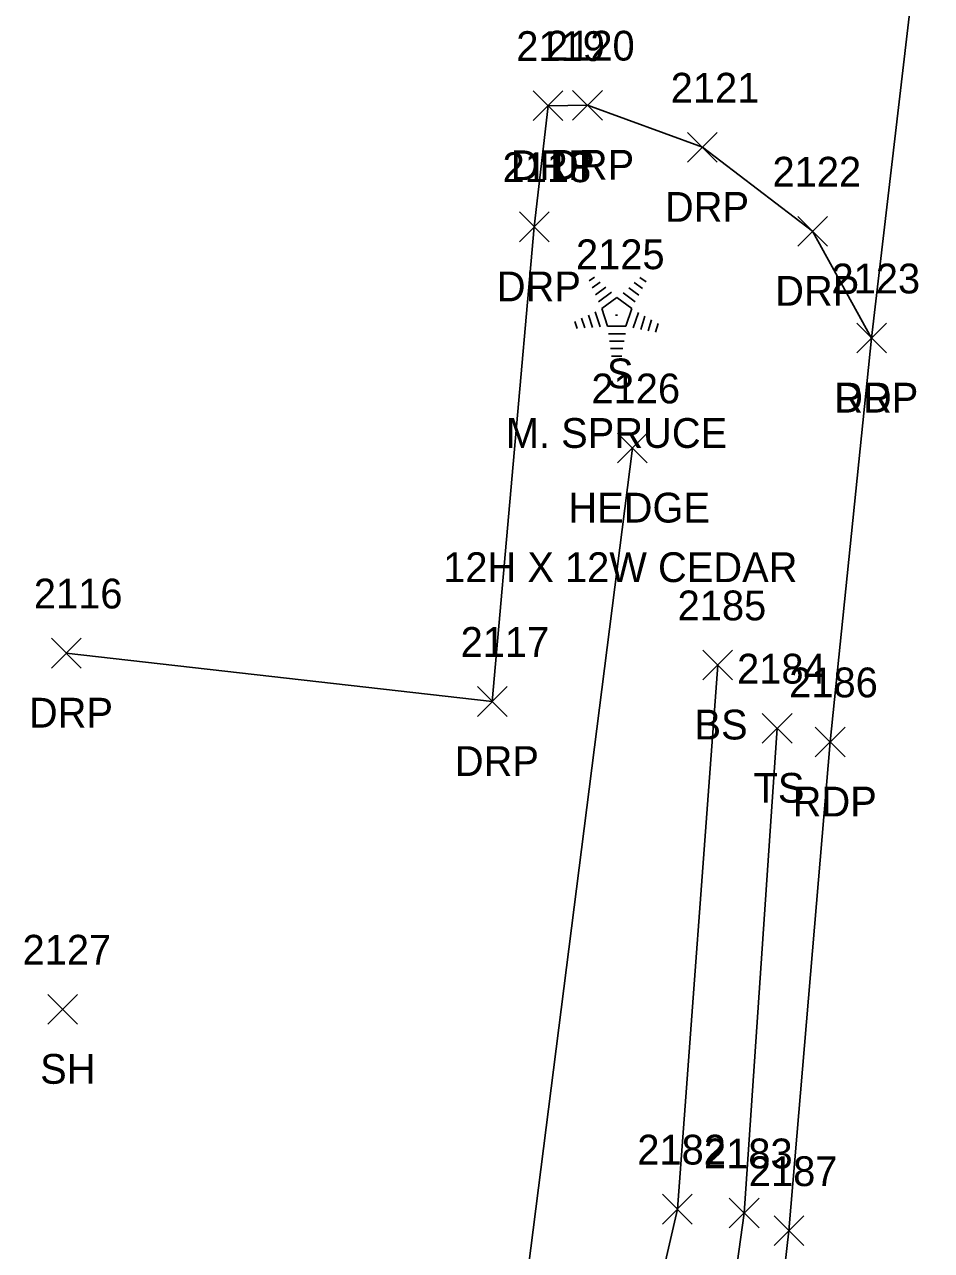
# Model space of a CAD drawing. Extents: x 1651305 to 1654558, y 539481 to 548441.
# Drawn here: x 1654302.3 to 1654363.2, y 544215.2 to 544297.6 of the extents above; entities that cross this region are included whole.
import ezdxf

# ---------------------------------------------------------------- set-up
doc = ezdxf.new("R2010")
doc.units = 0
for name, color, linetype in [('L_A', 7, 'Continuous'), ('L_C', 7, 'Continuous'), ('L_I', 7, 'Continuous'), ('L_TIC', 7, 'Continuous'), ('LAHR', 7, 'Continuous'), ('LELB', 7, 'Continuous'), ('LTC', 7, 'Continuous'), ('P_A', 7, 'Continuous'), ('P_I', 7, 'Continuous'), ('P_TIC', 7, 'Continuous'), ('PET', 7, 'Continuous'), ('R_A', 7, 'Continuous'), ('R_I', 7, 'Continuous'), ('R_TIC', 7, 'Continuous'), ('RDP', 7, 'Continuous')]:
    doc.layers.add(name, color=color, linetype=linetype)

msp = doc.modelspace()

# ---------------------------------------------------------------- linework, layer by layer
at = {"layer": 'L_TIC'}
for points in [[(1654342.12, 544268.118), (1654344.12, 544270.118)], [(1654344.12, 544268.118), (1654342.12, 544270.118)], [(1654347.847, 544253.55), (1654349.847, 544255.55)], [(1654349.847, 544253.55), (1654347.847, 544255.55)], [(1654351.841, 544249.303), (1654353.841, 544251.303)], [(1654353.841, 544249.303), (1654351.841, 544251.303)], [(1654303.88, 544230.43), (1654305.88, 544232.43)], [(1654305.88, 544230.43), (1654303.88, 544232.43)], [(1654345.141, 544217.007), (1654347.141, 544219.007)], [(1654347.141, 544217.007), (1654345.141, 544219.007)], [(1654349.618, 544216.751), (1654351.618, 544218.751)], [(1654351.618, 544216.751), (1654349.618, 544218.751)]]:
    msp.add_lwpolyline(points, dxfattribs=at)
at = {"layer": 'LAHR'}
msp.add_lwpolyline([(1654343.12, 544269.118), (1654333.903, 544196.537)], dxfattribs=at)
at = {"layer": 'LELB'}
for points in [[(1654340.212, 544192.32), (1654346.141, 544218.007), (1654348.847, 544254.55)], [(1654335.349, 544184.471), (1654346.097, 544185.222), (1654350.618, 544217.751), (1654352.841, 544250.303)]]:
    msp.add_lwpolyline(points, dxfattribs=at)
at = {"layer": 'LTC'}
for p, q in [((1654340.22, 544280.338), (1654340.575, 544280.596)), ((1654343.618, 544280.579), (1654344.038, 544280.274)), ((1654340.43, 544279.873), (1654340.959, 544280.257)), ((1654340.639, 544279.407), (1654341.343, 544279.918)), ((1654342.876, 544279.882), (1654343.555, 544279.388)), ((1654343.247, 544280.23), (1654343.797, 544279.831)), ((1654340.849, 544278.941), (1654341.727, 544279.579)), ((1654341.073, 544278.486), (1654342.085, 544279.221)), ((1654342.085, 544279.221), (1654343.082, 544278.496)), ((1654342.505, 544279.534), (1654343.315, 544278.945)), ((1654340.163, 544278.051), (1654340.435, 544277.216)), ((1654340.619, 544278.267), (1654340.95, 544277.248)), ((1654341.073, 544278.486), (1654341.46, 544277.293)), ((1654343.082, 544278.496), (1654342.691, 544277.293)), ((1654343.52, 544278.225), (1654343.182, 544277.186)), ((1654343.964, 544277.975), (1654343.677, 544277.09)), ((1654339.253, 544277.618), (1654339.405, 544277.15)), ((1654339.708, 544277.834), (1654339.92, 544277.183)), ((1654342.691, 544277.293), (1654341.46, 544277.293)), ((1654344.409, 544277.725), (1654344.172, 544276.995)), ((1654344.853, 544277.474), (1654344.666, 544276.9)), ((1654342.653, 544276.793), (1654341.508, 544276.793)), ((1654342.569, 544276.293), (1654341.58, 544276.293)), ((1654342.485, 544275.793), (1654341.653, 544275.793)), ((1654342.401, 544275.293), (1654341.726, 544275.293))]:
    msp.add_line(p, q, dxfattribs=at)
at = {"layer": 'P_TIC'}
for points in [[(1654358.176, 544275.501), (1654360.176, 544277.501)], [(1654360.176, 544275.501), (1654358.176, 544277.501)], [(1654355.39, 544248.38), (1654357.39, 544250.38)], [(1654357.39, 544248.38), (1654355.39, 544250.38)], [(1654352.626, 544215.56), (1654354.626, 544217.56)], [(1654354.626, 544215.56), (1654352.626, 544217.56)]]:
    msp.add_lwpolyline(points, dxfattribs=at)
at = {"layer": 'PET'}
msp.add_lwpolyline([(1654345.042, 544588.36), (1654352.836, 544566.031), (1654357.709, 544551.643), (1654360.669, 544540.213), (1654367.97, 544503.911), (1654371.191, 544473.217), (1654373.313, 544432.687), (1654372.374, 544396.626), (1654369.948, 544367.404), (1654366.855, 544341.544), (1654364.487, 544322.02), (1654359.176, 544276.501), (1654356.39, 544249.38), (1654353.626, 544216.56), (1654349.272, 544178.191), (1654347.294, 544164.707), (1654345.692, 544149.484), (1654340.924, 544117.477), (1654336.045, 544077.134)], dxfattribs=at)
at = {"layer": 'R_TIC'}
for points in [[(1654336.457, 544291.109), (1654338.457, 544293.109)], [(1654338.457, 544291.109), (1654336.457, 544293.109)], [(1654339.103, 544291.136), (1654341.103, 544293.136)], [(1654341.103, 544291.136), (1654339.103, 544293.136)], [(1654346.817, 544288.313), (1654348.817, 544290.313)], [(1654348.817, 544288.313), (1654346.817, 544290.313)], [(1654335.532, 544282.973), (1654337.532, 544284.973)], [(1654337.532, 544282.973), (1654335.532, 544284.973)], [(1654354.217, 544282.673), (1654356.217, 544284.673)], [(1654356.217, 544282.673), (1654354.217, 544284.673)], [(1654358.176, 544275.501), (1654360.176, 544277.501)], [(1654360.176, 544275.501), (1654358.176, 544277.501)], [(1654304.127, 544254.348), (1654306.127, 544256.348)], [(1654306.127, 544254.348), (1654304.127, 544256.348)], [(1654332.714, 544251.098), (1654334.714, 544253.098)], [(1654334.714, 544251.098), (1654332.714, 544253.098)]]:
    msp.add_lwpolyline(points, dxfattribs=at)
at = {"layer": 'RDP'}
msp.add_lwpolyline([(1654305.127, 544255.348), (1654333.714, 544252.098), (1654336.532, 544283.973), (1654337.457, 544292.109), (1654340.103, 544292.136), (1654347.817, 544289.313), (1654355.217, 544283.673), (1654359.176, 544276.501)], dxfattribs=at)

# ---------------------------------------------------------------- texts
at = {"layer": 'L_A'}
for s, p in [('S', (1654341.411, 544273.13)), ('HEDGE', (1654338.821, 544264.118)), ('BS', (1654347.288, 544249.55)), ('TS', (1654351.251, 544245.303)), ('SH', (1654303.368, 544226.43))]:
    msp.add_text(s, height=2, dxfattribs=at).set_placement(p)
at = {"layer": 'L_C'}
for s, p in [('M. SPRUCE', (1654334.623, 544269.13)), ('12H X 12W CEDAR', (1654330.42, 544260.118))]:
    msp.add_text(s, height=2, dxfattribs=at).set_placement(p)
at = {"layer": 'L_I'}
for s, p in [('2125', (1654339.332, 544281.13)), ('2126', (1654340.372, 544272.118)), ('2185', (1654346.154, 544257.55)), ('2184', (1654350.149, 544253.303)), ('2127', (1654302.187, 544234.43)), ('2182', (1654343.449, 544221.007)), ('2183', (1654347.925, 544220.751))]:
    msp.add_text(s, height=2, dxfattribs=at).set_placement(p)
at = {"layer": 'LTC'}
msp.add_text('.', height=1.037, rotation=270, dxfattribs=at).set_placement((1654341.968, 544278.234))
at = {"layer": 'P_A'}
for p in [(1654356.664, 544271.501), (1654353.878, 544244.38)]:
    msp.add_text('RDP', height=2, dxfattribs=at).set_placement(p)
at = {"layer": 'P_I'}
for s, p in [('2123', (1654356.483, 544279.501)), ('2186', (1654353.642, 544252.38)), ('2187', (1654350.934, 544219.56))]:
    msp.add_text(s, height=2, dxfattribs=at).set_placement(p)
at = {"layer": 'R_A'}
for p in [(1654334.945, 544287.109), (1654337.591, 544287.136), (1654345.305, 544284.313), (1654334.02, 544278.973), (1654352.705, 544278.673), (1654356.664, 544271.501), (1654302.615, 544250.348), (1654331.202, 544247.098)]:
    msp.add_text('DRP', height=2, dxfattribs=at).set_placement(p)
at = {"layer": 'R_I'}
for s, p in [('2119', (1654335.324, 544295.109)), ('2120', (1654337.324, 544295.136)), ('2121', (1654345.691, 544292.313)), ('2118', (1654334.406, 544286.973)), ('2122', (1654352.524, 544286.673)), ('2123', (1654356.483, 544279.501)), ('2116', (1654302.946, 544258.348)), ('2117', (1654331.588, 544255.098))]:
    msp.add_text(s, height=2, dxfattribs=at).set_placement(p)

doc.saveas('drawing.dxf')
